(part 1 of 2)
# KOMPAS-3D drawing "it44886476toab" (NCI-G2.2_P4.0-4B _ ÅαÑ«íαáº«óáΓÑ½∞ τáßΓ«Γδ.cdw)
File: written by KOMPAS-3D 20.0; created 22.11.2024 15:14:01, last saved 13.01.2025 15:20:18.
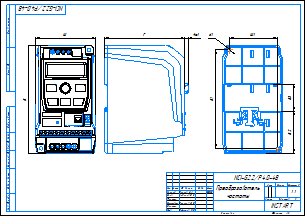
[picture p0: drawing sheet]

Sheet 1: A3, landscape

Document properties: Автор: admin; Полное имя файла: C:\Уралов Работа\Уралов (локальная)\ПЧ\! Китай 3Д-модель NCI\NCI 0.75-2.2 4B\NCI 0.75-2.2 4B.m3d

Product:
- Part/product: it44886476toab
    Масса: 2.32322
  - Body: Тело 17
      Масса: 0.0117014
  - Body: Тело 374
      Масса: 5.48304e-05
  - Body: Тело 265
      Масса: 1.32696e-05
  - Body: Тело 266
      Масса: 1.7366e-05
  - Body: Тело 267
      Масса: 1.7366e-05
  - Body: Тело 103
      Масса: 1.32696e-05
  - Body: Тело 573
      Масса: 4.06595e-05
  - Body: Тело 348
      Масса: 1.32696e-05
  - Body: Тело 270
      Масса: 1.7366e-05
  - Body: Тело 77
      Масса: 1.32696e-05
  - Body: Тело 244
      Масса: 1.65581e-05
  - Body: Тело 536
      Масса: 0.000158536
  - Body: Тело 377
      Масса: 1.65581e-05
  - Body: Тело 272
      Масса: 1.7366e-05
  - Body: Тело 273
      Масса: 5.48304e-05
  - Body: Тело 238
      Масса: 1.7366e-05
  - Body: Тело 274
      Масса: 1.7366e-05
  - Body: Тело 277
      Масса: 1.7366e-05
  - Body: Тело 530
      Масса: 5.61948e-05
  - Body: Тело 278
      Масса: 1.7366e-05
  - Body: Тело 282
      Масса: 1.7366e-05
  - Body: Тело 477
      Масса: 1.51773e-05
  - Body: Тело 526
      Масса: 5.61948e-05
  - Body: Тело 391
      Масса: 1.32696e-05
  - Body: Тело 285
      Масса: 5.48304e-05
  - Body: Тело 287
      Масса: 1.32696e-05
  - Body: Тело 290
      Масса: 0.000413213
  - Body: Тело 269
      Масса: 5.48304e-05
  - Body: Тело 292
      Масса: 1.7366e-05
  - Body: Тело 33
      Масса: 0.00516019
  - Body: Тело 252
      Масса: 5.48304e-05
  - Body: Тело 294
      Масса: 0.000413213
  - Body: Тело 297
      Масса: 3.64631e-05
  - Body: Тело 299
      Масса: 3.64028e-05
  - Body: Тело 283
      Масса: 1.7366e-05
  - Body: Тело 300
      Масса: 1.65581e-05
  - Body: Тело 303
      Масса: 1.65581e-05
  - Body: Тело 516
      Масса: 0.00507377
  - Body: Тело 384
      Масса: 5.48304e-05
  - Body: Тело 360
      Масса: 1.32696e-05
  - Body: Тело 347
      Масса: 1.32696e-05
  - Body: Тело 304
      Масса: 1.65581e-05
  - Body: Тело 307
      Масса: 0.000213463
  - Body: Тело 308
      Масса: 0.000413213
  - Body: Тело 180
      Масса: 1.32696e-05
  - Body: Тело 240
      Масса: 1.7366e-05
  - Body: Тело 309
      Масса: 1.32696e-05
  - Body: Тело 473
      Масса: 0.00425494
  - Body: Тело 311
      Масса: 5.48304e-05
  - Body: Тело 122
      Масса: 1.65581e-05
  - Body: Тело 560
      Масса: 1.65581e-05
  - Body: Тело 312
      Масса: 5.48304e-05
  - Body: Тело 317
      Масса: 1.32696e-05
  - Body: Тело 318
      Масса: 1.32696e-05
  - Body: Тело 321
      Масса: 1.32696e-05
  - Body: Тело 324
      Масса: 1.32696e-05
  - Body: Тело 480
      Масса: 1.51773e-05
  - Body: Тело 288
      Масса: 1.7366e-05
  - Body: Тело 293
      Масса: 5.48304e-05
  - Body: Тело 325
      Масса: 1.32696e-05
  - Body: Тело 99
      Масса: 1.65581e-05
  - Body: Тело 617
      Масса: 1.63919e-05
  - Body: Тело 327
      Масса: 1.32696e-05
  - Body: Тело 31
      Масса: 0.0078835
  - Body: Тело 100
      Масса: 1.65581e-05
  - Body: Тело 105
      Масса: 1.32696e-05
  - Body: Тело 328
      Масса: 1.7366e-05
  - Body: Тело 301
      Масса: 1.65581e-05
  - Body: Тело 331
      Масса: 1.7366e-05
  - Body: Тело 332
      Масса: 1.7366e-05
  - Body: Тело 446
      Масса: 0.000307437
  - Body: Тело 337
      Масса: 1.7366e-05
  - Body: Тело 338
      Масса: 1.7366e-05
  - Body: Тело 570
      Масса: 4.06595e-05
  - Body: Тело 340
      Масса: 1.32696e-05
  - Body: Тело 196
      Масса: 1.32696e-05
  - Body: Тело 357
      Масса: 1.65581e-05
  - Body: Тело 346
      Масса: 1.32696e-05
  - Body: Тело 335
      Масса: 1.32696e-05
  - Body: Тело 281
      Масса: 1.32696e-05
  - Body: Тело 362
      Масса: 1.32696e-05
  - Body: Тело 353
      Масса: 1.7366e-05
  - Body: Тело 355
      Масса: 5.48304e-05
  - Body: Тело 466
      Масса: 0.00829114
  - Body: Тело 358
      Масса: 5.48304e-05
  - Body: Тело 359
      Масса: 1.7366e-05
  - Body: Тело 286
      Масса: 1.7366e-05
  - Body: Тело 86
      Масса: 1.32696e-05
  - Body: Тело 310
      Масса: 1.7366e-05
  - Body: Тело 368
      Масса: 1.32696e-05
  - Body: Тело 370
      Масса: 1.32696e-05
  - Body: Тело 333
      Масса: 1.32696e-05
  - Body: Тело 628
      Масса: 1.51773e-05
  - Body: Тело 371
      Масса: 1.7366e-05
  - Body: Тело 75
      Масса: 1.32696e-05
  - Body: Тело 373
      Масса: 1.32696e-05
  - Body: Тело 375
      Масса: 1.32696e-05
  - Body: Тело 351
      Масса: 2.90876e-05
  - Body: Тело 76
      Масса: 1.65581e-05
  - Body: Тело 259
      Масса: 1.7366e-05
  - Body: Тело 378
      Масса: 0.000413213
  - Body: Тело 95
      Масса: 0.000935996
  - Body: Тело 372
      Масса: 1.7366e-05
  - Body: Тело 322
      Масса: 1.32696e-05
  - Body: Тело 380
      Масса: 1.32696e-05
  - Body: Тело 639
      Масса: 1.63919e-05
  - Body: Тело 385
      Масса: 1.32696e-05
  - Body: Тело 291
      Масса: 0.000213463
  - Body: Тело 386
      Масса: 1.32696e-05
  - Body: Тело 229
      Масса: 1.32696e-05
  - Body: Тело 388
      Масса: 1.32696e-05
  - Body: Тело 389
      Масса: 1.65581e-05
  - Body: Тело 93
      Масса: 3.83377e-05
  - Body: Тело 390
      Масса: 1.65581e-05
  - Body: Тело 143
      Масса: 1.32696e-05
  - Body: Тело 394
      Масса: 1.32696e-05
  - Body: Тело 395
      Масса: 1.32696e-05
  - Body: Тело 354
      Масса: 0.000213463
  - Body: Тело 396
      Масса: 1.7366e-05
  - Body: Тело 397
      Масса: 1.32696e-05
  - Body: Тело 398
      Масса: 1.65581e-05
  - Body: Тело 479
      Масса: 1.51773e-05
  - Body: Тело 402
      Масса: 1.7366e-05
  - Body: Тело 59
      Масса: 1.32696e-05
  - Body: Тело 339
      Масса: 1.32696e-05
  - Body: Тело 404
      Масса: 1.32696e-05
  - Body: Тело 89
      Масса: 0.00142218
  - Body: Тело 406
      Масса: 1.65581e-05
  - Body: Тело 393
      Масса: 1.32696e-05
  - Body: Тело 52
      Масса: 1.32696e-05
  - Body: Тело 407
      Масса: 5.48304e-05
  - Body: Тело 97
      Масса: 0.0015961
  - Body: Тело 410
      Масса: 5.48304e-05
  - Body: Тело 636
      Масса: 1.65581e-05
  - Body: Тело 412
      Масса: 1.7366e-05
  - Body: Тело 413
      Масса: 1.32696e-05
  - Body: Тело 414
      Масса: 1.32696e-05
  - Body: Тело 537
      Масса: 0.000158536
  - Body: Тело 415
      Масса: 1.7366e-05
  - Body: Тело 235
      Масса: 1.7366e-05
  - Body: Тело 419
      Масса: 1.32696e-05
  - Body: Тело 648
      Масса: 0.00426189
  - Body: Тело 420
      Масса: 1.7366e-05
  - Body: Тело 186
      Масса: 1.32696e-05
  - Body: Тело 422
      Масса: 5.48304e-05
  - Body: Тело 381
      Масса: 1.7366e-05
  - Body: Тело 423
      Масса: 1.32696e-05
  - Body: Тело 424
      Масса: 1.7366e-05
  - Body: Тело 98
      Масса: 1.65581e-05
  - Body: Тело 305
      Масса: 1.65581e-05
  - Body: Тело 425
      Масса: 1.32696e-05
  - Body: Тело 365
      Масса: 1.32696e-05
  - Body: Тело 271
      Масса: 1.32696e-05
  - Body: Тело 206
      Масса: 1.32696e-05
  - Body: Тело 429
      Масса: 0.146258
  - Body: Тело 334
      Масса: 1.7366e-05
  - Body: Тело 430
      Масса: 0.146258
  - Body: Тело 350
      Масса: 1.7366e-05
  - Body: Тело 345
      Масса: 1.32696e-05
  - Body: Тело 431
      Масса: 0.146258
  - Body: Тело 364
      Масса: 1.32696e-05
  - Body: Тело 329
      Масса: 1.32696e-05
  - Body: Тело 434
      Масса: 0.000355433
  - Body: Тело 5
      Масса: 0.000355433
  - Body: Тело 124
      Масса: 1.65581e-05
  - Body: Тело 344
      Масса: 1.32696e-05
  - Body: Тело 436
      Масса: 0.000355433
  - Body: Тело 439
      Масса: 0.00113358
  - Body: Тело 606
      Масса: 0.000137594
  - Body: Тело 323
      Масса: 1.32696e-05
  - Body: Тело 441
      Масса: 0.00113358
  - Body: Тело 442
      Масса: 0.000355433
  - Body: Тело 554
      Масса: 4.06595e-05
  - Body: Тело 444
      Масса: 0.000355433
  - Body: Тело 246
      Масса: 1.65581e-05
  - Body: Тело 445
      Масса: 0.00113358
  - Body: Тело 438
      Масса: 0.000355433
  - Body: Тело 106
      Масса: 1.32696e-05
  - Body: Тело 508
      Масса: 1.51773e-05
  - Body: Тело 577
      Масса: 1.7366e-05
  - Body: Тело 392
      Масса: 1.32696e-05
  - Body: Тело 193
      Масса: 1.32696e-05
  - Body: Тело 448
      Масса: 0.000307437
  - Body: Тело 481
      Масса: 1.51773e-05
  - Body: Тело 450
      Масса: 6.34685e-05
  - Body: Тело 222
      Масса: 1.32696e-05
  - Body: Тело 315
      Масса: 1.7366e-05
  - Body: Тело 452
      Масса: 1.63919e-05
  - Body: Тело 53
      Масса: 1.32696e-05
  - Body: Тело 401
      Масса: 1.32696e-05
  - Body: Тело 418
      Масса: 1.7366e-05
  - Body: Тело 517
      Масса: 0.00106884
  - Body: Тело 417
      Масса: 1.32696e-05
  - Body: Тело 453
      Масса: 1.63919e-05
  - Body: Тело 454
      Масса: 0.000382752
  - Body: Тело 428
      Масса: 0.146258
  - Body: Тело 455
      Масса: 1.51773e-05
  - Body: Тело 539
      Масса: 1.51773e-05
  - Body: Тело 457
      Масса: 1.51773e-05
  - Body: Тело 459
      Масса: 3.90329e-05
  - Body: Тело 557
      Масса: 0.00166679
  - Body: Тело 569
      Масса: 1.32696e-05
  - Body: Тело 578
      Масса: 1.32696e-05
  - Body: Тело 626
      Масса: 1.32696e-05
  - Body: Тело 134
      Масса: 1.32696e-05
  - Body: Тело 582
      Масса: 1.65581e-05
  - Body: Тело 203
      Масса: 1.32696e-05
  - Body: Тело 572
      Масса: 1.32696e-05
  - Body: Тело 567
      Масса: 1.32696e-05
  - Body: Тело 207
      Масса: 1.32696e-05
  - Body: Тело 645
      Масса: 1.32696e-05
  - Body: Тело 559
      Масса: 1.65581e-05
  - Body: Тело 152
      Масса: 1.32696e-05
  - Body: Тело 449
      Масса: 0.0658364
  - Body: Тело 316
      Масса: 1.32696e-05
  - Body: Тело 376
      Масса: 1.32696e-05
  - Body: Тело 575
      Масса: 1.32696e-05
  - Body: Тело 576
      Масса: 1.32696e-05
  - Body: Тело 85
      Масса: 1.32696e-05
  - Body: Тело 574
      Масса: 4.06595e-05
  - Body: Тело 399
      Масса: 1.32696e-05
  - Body: Тело 320
      Масса: 1.32696e-05
  - Body: Тело 275
      Масса: 1.7366e-05
  - Body: Тело 213
      Масса: 1.32696e-05
  - Body: Тело 625
      Масса: 1.32696e-05
  - Body: Тело 644
      Масса: 0.000158536
  - Body: Тело 584
      Масса: 4.06595e-05
  - Body: Тело 70
      Масса: 1.65581e-05
  - Body: Тело 588
      Масса: 1.32696e-05
  - Body: Тело 276
      Масса: 1.7366e-05
  - Body: Тело 363
      Масса: 1.32696e-05
  - Body: Тело 474
      Масса: 1.51773e-05
  - Body: Тело 548
      Масса: 2.98222e-05
  - Body: Тело 409
      Масса: 5.48304e-05
  - Body: Тело 472
      Масса: 0.00329327
  - Body: Тело 533
      Масса: 5.61948e-05
  - Body: Тело 647
      Масса: 0.00426189
  - Body: Тело 586
      Масса: 1.32696e-05
  - Body: Тело 262
      Масса: 1.7366e-05
  - Body: Тело 562
      Масса: 0.000382752
  - Body: Тело 379
      Масса: 1.32696e-05
  - Body: Тело 632
      Масса: 1.51773e-05
  - Body: Тело 565
      Масса: 4.06595e-05
  - Body: Тело 118
      Масса: 0.000413213
  - Body: Тело 597
      Масса: 7.12116e-06
  - Body: Тело 613
      Масса: 1.63919e-05
  - Body: Тело 387
      Масса: 1.32696e-05
  - Body: Тело 593
      Масса: 1.32696e-05
  - Body: Тело 408
      Масса: 5.48304e-05
  - Body: Тело 109
      Масса: 1.32696e-05
  - Body: Тело 163
      Масса: 1.32696e-05
  - Body: Тело 488
      Масса: 1.51773e-05
  - Body: Тело 367
      Масса: 1.32696e-05
  - Body: Тело 411
      Масса: 5.48304e-05
  - Body: Тело 583
      Масса: 4.06595e-05
  - Body: Тело 598
      Масса: 7.12116e-06
  - Body: Тело 551
      Масса: 0.000255388
  - Body: Тело 405
      Масса: 1.32696e-05
  - Body: Тело 619
      Масса: 1.32696e-05
  - Body: Тело 361
      Масса: 1.32696e-05
  - Body: Тело 589
      Масса: 1.32696e-05
  - Body: Тело 499
      Масса: 1.51773e-05
  - Body: Тело 440
      Масса: 0.000355433
  - Body: Тело 640
      Масса: 1.63919e-05
  - Body: Тело 150
      Масса: 1.32696e-05
  - Body: Тело 568
      Масса: 1.32696e-05
  - Body: Тело 194
      Масса: 1.32696e-05
  - Body: Тело 251
      Масса: 1.7366e-05
  - Body: Тело 342
      Масса: 0.00166679
  - Body: Тело 604
      Масса: 5.61948e-05
  - Body: Тело 650
      Масса: 0.00426189
  - Body: Тело 161
      Масса: 1.32696e-05
  - Body: Тело 611
      Масса: 0.000158536
  - Body: Тело 210
      Масса: 1.32696e-05
  - Body: Тело 540
      Масса: 1.51773e-05
  - Body: Тело 296
      Масса: 3.6965e-05
  - Body: Тело 601
      Масса: 5.61948e-05
  - Body: Тело 484
      Масса: 0.000158536
  - Body: Тело 622
      Масса: 1.32696e-05
  - Body: Тело 527
      Масса: 0.000141095
  - Body: Тело 624
      Масса: 1.32696e-05
  - Body: Тело 121
      Масса: 0.000413213
  - Body: Тело 600
      Масса: 5.61948e-05
  - Body: Тело 603
      Масса: 5.61948e-05
  - Body: Тело 607
      Масса: 1.32696e-05
  - Body: Тело 289
      Масса: 1.7366e-05
  - Body: Тело 471
      Масса: 0.00329327
  - Body: Тело 313
      Масса: 1.7366e-05
  - Body: Тело 591
      Масса: 7.12116e-06
  - Body: Тело 356
      Масса: 1.65581e-05
  - Body: Тело 306
      Масса: 1.65581e-05
  - Body: Тело 541
      Масса: 0.000158536
  - Body: Тело 511
      Масса: 1.51773e-05
  - Body: Тело 160
      Масса: 1.32696e-05
  - Body: Тело 566
      Масса: 1.32696e-05
  - Body: Тело 563
      Масса: 4.06595e-05
  - Body: Тело 638
      Масса: 1.7366e-05
  - Body: Тело 489
      Масса: 1.51773e-05
  - Body: Тело 456
      Масса: 1.51773e-05
  - Body: Тело 485
      Масса: 0.000158536
  - Body: Тело 284
      Масса: 1.7366e-05
  - Body: Тело 138
      Масса: 2.23009e-05
  - Body: Тело 225
      Масса: 1.32696e-05
  - Body: Тело 546
      Масса: 0.000255388
  - Body: Тело 113
      Масса: 0.000413213
  - Body: Тело 642
      Масса: 3.90329e-05
  - Body: Тело 618
      Масса: 1.63919e-05
  - Body: Тело 525
      Масса: 0.000213463
  - Body: Тело 164
      Масса: 1.32696e-05
  - Body: Тело 253
      Масса: 1.7366e-05
  - Body: Тело 561
      Масса: 1.65581e-05
  - Body: Тело 594
      Масса: 1.32696e-05
  - Body: Тело 482
      Масса: 1.51773e-05
  - Body: Тело 81
      Масса: 1.32696e-05
  - Body: Тело 280
      Масса: 1.32696e-05
  - Body: Тело 494
      Масса: 1.51773e-05
  - Body: Тело 641
      Масса: 3.90329e-05
  - Body: Тело 564
      Масса: 4.06595e-05
  - Body: Тело 633
      Масса: 1.51773e-05
  - Body: Тело 518
      Масса: 0.00166679
  - Body: Тело 620
      Масса: 1.7366e-05
  - Body: Тело 497
      Масса: 1.51773e-05
  - Body: Тело 151
      Масса: 1.65581e-05
  - Body: Тело 302
      Масса: 1.65581e-05
  - Body: Тело 110
      Масса: 1.32696e-05
  - Body: Тело 646
      Масса: 0.000137594
  - Body: Тело 264
      Масса: 1.7366e-05
  - Body: Тело 635
      Масса: 1.65581e-05
  - Body: Тело 608
      Масса: 0.00166679
  - Body: Тело 460
      Масса: 3.90329e-05
  - Body: Тело 403
      Масса: 1.7366e-05
  - Body: Тело 612
      Масса: 0.000158536
  - Body: Тело 492
      Масса: 1.51773e-05
  - Body: Тело 139
      Масса: 0.000194606
  - Body: Тело 400
      Масса: 1.7366e-05
  - Body: Тело 605
      Масса: 5.61948e-05
  - Body: Тело 623
      Масса: 1.32696e-05
  - Body: Тело 117
      Масса: 0.000413213
  - Body: Тело 185
      Масса: 1.32696e-05
  - Body: Тело 631
      Масса: 1.51773e-05
  - Body: Тело 580
      Масса: 1.32696e-05
  - Body: Тело 349
      Масса: 1.7366e-05
  - Body: Тело 621
      Масса: 1.32696e-05
  - Body: Тело 627
      Масса: 0.000255388
  - Body: Тело 531
      Масса: 5.61948e-05
  - Body: Тело 649
      Масса: 0.00426189
  - Body: Тело 585
      Масса: 4.06595e-05
  - Body: Тело 236
      Масса: 1.7366e-05
  - Body: Тело 513
      Масса: 1.51773e-05
  - Body: Тело 426
      Масса: 1.32696e-05
  - Body: Тело 341
      Масса: 0.00166679
  - Body: Тело 470
      Масса: 0.00329329
  - Body: Тело 382
      Масса: 5.48304e-05
  - Body: Тело 227
      Масса: 1.32696e-05
  - Body: Тело 476
      Масса: 1.51773e-05
  - Body: Тело 538
      Масса: 1.51773e-05
  - Body: Тело 596
      Масса: 1.32696e-05
  - Body: Тело 609
      Масса: 1.7366e-05
  - Body: Тело 610
      Масса: 0.00166679
  - Body: Тело 263
      Масса: 1.7366e-05
  - Body: Тело 629
      Масса: 1.51773e-05
  - Body: Тело 336
      Масса: 3.64028e-05
  - Body: Тело 495
      Масса: 1.51773e-05
  - Body: Тело 168
      Масса: 1.32696e-05
  - Body: Тело 298
      Масса: 3.64495e-05
  - Body: Тело 279
      Масса: 1.32696e-05
  - Body: Тело 72
      Масса: 1.65581e-05
  - Body: Тело 500
      Масса: 1.51773e-05
  - Body: Тело 505
      Масса: 1.51773e-05
  - Body: Тело 558
      Масса: 0.00726683
  - Body: Тело 630
      Масса: 1.51773e-05
  - Body: Тело 602
      Масса: 5.61948e-05
  - Body: Тело 556
      Масса: 0.00166679
  - Body: Тело 555
      Масса: 0.00166679
  - Body: Тело 634
      Масса: 1.51773e-05
  - Body: Тело 435
      Масса: 0.00113358
  - Body: Тело 416
      Масса: 1.7366e-05
  - Body: Тело 190
      Масса: 1.32696e-05
  - Body: Тело 330
      Масса: 1.7366e-05
  - Body: Тело 28
      Масса: 0.00135688
  - Body: Тело 553
      Масса: 4.06595e-05
  - Body: Тело 176
      Масса: 1.32696e-05
  - Body: Тело 552
      Масса: 4.06595e-05
  - Body: Тело 534
      Масса: 1.32696e-05
  - Body: Тело 595
      Масса: 1.32696e-05
  - Body: Тело 23
      Масса: 0.0243258
  - Body: Тело 247
      Масса: 1.7366e-05
  - Body: Тело 314
      Масса: 1.7366e-05
  - Body: Тело 126
      Масса: 0.000512664
  - Body: Тело 157
      Масса: 1.32696e-05
  - Body: Тело 550
      Масса: 0.000255388
  - Body: Тело 32
      Масса: 0.0135217
  - Body: Тело 592
      Масса: 7.12116e-06
  - Body: Тело 366
      Масса: 1.7366e-05
  - Body: Тело 504
      Масса: 1.51773e-05
  - Body: Тело 258
      Масса: 1.7366e-05
  - Body: Тело 421
      Масса: 1.7366e-05
  - Body: Тело 35
      Масса: 0.262997
  - Body: Тело 204
      Масса: 1.32696e-05
  - Body: Тело 549
      Масса: 0.000255388
  - Body: Тело 257
      Масса: 1.7366e-05
  - Body: Тело 614
      Масса: 1.63919e-05
  - Body: Тело 547
      Масса: 0.000255388
  - Body: Тело 41
      Масса: 0.0119524
  - Body: Тело 71
      Масса: 1.65581e-05
  - Body: Тело 506
      Масса: 1.51773e-05
  - Body: Тело 545
      Масса: 1.51773e-05
  - Body: Тело 145
      Масса: 1.32696e-05
  - Body: Тело 461
      Масса: 0.000404362
  - Body: Тело 502
      Масса: 1.51773e-05
  - Body: Тело 352
      Масса: 2.90876e-05
  - Body: Тело 120
      Масса: 0.000413213
  - Body: Тело 295
      Масса: 1.65581e-05
  - Body: Тело 544
      Масса: 0.000158536
  - Body: Тело 469
      Масса: 0.0113891
  - Body: Тело 146
      Масса: 1.32696e-05
  - Body: Тело 149
      Масса: 1.32696e-05
  - Body: Тело 615
      Масса: 1.63919e-05
  - Body: Тело 543
      Масса: 0.000158536
  - Body: Тело 542
      Масса: 0.000158536
  - Body: Тело 462
      Масса: 0.000404362
  - Body: Тело 616
      Масса: 1.63919e-05
  - Body: Тело 343
      Масса: 0.00166679
  - Body: Тело 532
      Масса: 5.61948e-05
  - Body: Тело 493
      Масса: 1.51773e-05
  - Body: Тело 529
      Масса: 5.61948e-05
  - Body: Тело 579
      Масса: 0.00017125
  - Body: Тело 200
      Масса: 1.32696e-05
  - Body: Тело 239
      Масса: 5.48304e-05
  - Body: Тело 443
      Масса: 0.00113358
  - Body: Тело 216
      Масса: 0.000280294
  - Body: Тело 468
      Масса: 0.0253857
  - Body: Тело 64
      Масса: 1.65581e-05
  - Body: Тело 528
      Масса: 0.000141095
  - Body: Тело 599
      Масса: 7.12116e-06
  - Body: Тело 590
      Масса: 1.32696e-05
  - Body: Тело 191
      Масса: 1.32696e-05
  - Body: Тело 523
      Масса: 0.000255388
  - Body: Тело 458
      Масса: 1.51773e-05
  - Body: Тело 319
      Масса: 1.32696e-05
  - Body: Тело 49
      Масса: 0.00944
  - Body: Тело 522
      Масса: 1.65581e-05
  - Body: Тело 521
      Масса: 1.32696e-05
  - Body: Тело 571
      Масса: 0.00166679
  - Body: Тело 509
      Масса: 1.51773e-05
  - Body: Тело 326
      Масса: 1.32696e-05
  - Body: Тело 520
      Масса: 5.48304e-05
  - Body: Тело 427
      Масса: 1.32696e-05
  - Body: Тело 519
      Масса: 1.7366e-05
  - Body: Тело 637
      Масса: 1.51773e-05
  - Body: Тело 524
      Масса: 1.65581e-05
  - Body: Тело 432
      Масса: 0.000118347
  - Body: Тело 487
      Масса: 1.65581e-05
  - Body: Тело 510
      Масса: 1.51773e-05
  - Body: Тело 515
      Масса: 0.00507372
  - Body: Тело 512
      Масса: 1.51773e-05
  - Body: Тело 155
      Масса: 1.32696e-05
  - Body: Тело 587
      Масса: 1.32696e-05
  - Body: Тело 174
      Масса: 1.65581e-05
  - Body: Тело 507
      Масса: 1.51773e-05
  - Body: Тело 12
      Масса: 0.000703761
  - Body: Тело 187
      Масса: 1.32696e-05
  - Body: Тело 447
      Масса: 0.000307437
  - Body: Тело 503
      Масса: 1.51773e-05
  - Body: Тело 501
      Масса: 1.51773e-05
  - Body: Тело 369
      Масса: 1.32696e-05
  - Body: Тело 60
      Масса: 1.32696e-05
  - Body: Тело 498
      Масса: 1.51773e-05
  - Body: Тело 535
      Масса: 1.52051e-05
  - Body: Тело 437
      Масса: 0.00113358
  - Body: Тело 496
      Масса: 1.51773e-05
  - Body: Тело 433
      Масса: 0.000118347
  - Body: Тело 491
      Масса: 1.65581e-05
  - Body: Тело 490
      Масса: 1.51773e-05
  - Body: Тело 581
      Масса: 1.65581e-05
  - Body: Тело 486
      Масса: 0.000158536
  - Body: Тело 483
      Масса: 1.51773e-05
  - Body: Тело 514
      Масса: 1.51773e-05
  - Body: Тело 643
      Масса: 0.000158536
  - Body: Тело 125
      Масса: 1.65581e-05
  - Body: Тело 383
      Масса: 0.000340816
  - Body: Тело 465
      Масса: 0.00829114
  - Body: Тело 478
      Масса: 1.51773e-05
  - Body: Тело 451
      Масса: 6.34685e-05
  - Body: Тело 475
      Масса: 1.51773e-05
  - Body: Тело 467
      Масса: 0.00436982
  - Body: Тело 268
      Масса: 5.48304e-05
  - Body: Тело 464
      Масса: 0.00829425
  - Body: Тело 226
      Масса: 0.000413213
  - Body: Тело 463
      Масса: 0.000404362
  - Body: Тело 170
      Масса: 1.32696e-05
  - Body: Тело 261
      Масса: 3.83377e-05
  - Body: Тело 260
      Масса: 1.7366e-05
  - Body: Тело 167
      Масса: 1.32696e-05
  - Body: Тело 256
      Масса: 1.7366e-05
  - Body: Тело 119
      Масса: 0.000413213
  - Body: Тело 255
      Масса: 1.7366e-05
  - Body: Тело 254
      Масса: 1.32696e-05
  - Body: Тело 250
      Масса: 1.7366e-05
  - Body: Тело 249
      Масса: 1.7366e-05
  - Body: Тело 248
      Масса: 1.7366e-05
  - Body: Тело 19
      Масса: 0.0117014
  - Body: Тело 114
      Масса: 0.000413213
  - Body: Тело 234
      Масса: 1.7366e-05
  - Body: Тело 245
      Масса: 1.65581e-05
  - Body: Тело 243
      Масса: 1.65581e-05
  - Body: Тело 242
      Масса: 1.65581e-05
  - Body: Тело 65
      Масса: 1.65581e-05
  - Body: Тело 241
      Масса: 0.000424983
  - Body: Тело 141
      Масса: 0.000213463
  - Body: Тело 237
      Масса: 1.7366e-05
  - Body: Тело 1
      Масса: 0.00113358
  - Body: Тело 233
      Масса: 1.7366e-05
  - Body: Тело 232
      Масса: 5.48304e-05
  - Body: Тело 231
      Масса: 0.00398049
  - Body: Тело 230
      Масса: 1.32696e-05
  - Body: Тело 184
      Масса: 1.32696e-05
  - Body: Тело 228
      Масса: 1.32696e-05
  - Body: Тело 224
      Масса: 1.32696e-05
  - Body: Тело 162
      Масса: 1.65581e-05
  - Body: Тело 223
      Масса: 1.32696e-05
  - Body: Тело 221
      Масса: 1.65581e-05
  - Body: Тело 220
      Масса: 1.32696e-05
  - Body: Тело 219
      Масса: 1.32696e-05
  - Body: Тело 218
      Масса: 1.32696e-05
  - Body: Тело 217
      Масса: 1.32696e-05
  - Body: Тело 215
      Масса: 1.65581e-05
  - Body: Тело 9
      Масса: 0.000703761
  - Body: Тело 214
      Масса: 1.32696e-05
  - Body: Тело 212
      Масса: 1.32696e-05
  - Body: Тело 211
      Масса: 1.32696e-05
  - Body: Тело 209
      Масса: 1.32696e-05
  - Body: Тело 208
      Масса: 1.7366e-05
  - Body: Тело 205
      Масса: 1.32696e-05
  - Body: Тело 202
      Масса: 1.32696e-05
  - Body: Тело 201
      Масса: 1.32696e-05
  - Body: Тело 29
      Масса: 0.00135688
  - Body: Тело 199
      Масса: 1.32696e-05
  - Body: Тело 198
      Масса: 1.32696e-05
  - Body: Тело 197
      Масса: 1.32696e-05
  - Body: Тело 195
      Масса: 1.32696e-05
  - Body: Тело 192
      Масса: 1.32696e-05
  - Body: Тело 189
      Масса: 1.32696e-05
  - Body: Тело 188
      Масса: 1.32696e-05
  - Body: Тело 183
      Масса: 1.32696e-05
  - Body: Тело 182
      Масса: 1.32696e-05
  - Body: Тело 181
      Масса: 1.32696e-05
  - Body: Тело 179
      Масса: 1.32696e-05
  - Body: Тело 178
      Масса: 1.32696e-05
  - Body: Тело 44
      Масса: 0.0119524
  - Body: Тело 50
      Масса: 0.00101975
  - Body: Тело 177
      Масса: 1.32696e-05
  - Body: Тело 175
      Масса: 1.32696e-05
  - Body: Тело 45
      Масса: 0.0267013
  - Body: Тело 137
      Масса: 1.32696e-05
  - Body: Тело 173
      Масса: 1.32696e-05
  - Body: Тело 172
      Масса: 1.65581e-05
  - Body: Тело 153
      Масса: 1.32696e-05
  - Body: Тело 171
      Масса: 1.32696e-05
  - Body: Тело 169
      Масса: 1.32696e-05
  - Body: Тело 140
      Масса: 0.000213463
  - Body: Тело 166
      Масса: 1.32696e-05
  - Body: Тело 165
      Масса: 1.65581e-05
  - Body: Тело 159
      Масса: 1.32696e-05
  - Body: Тело 116
      Масса: 0.000413213
  - Body: Тело 158
      Масса: 1.32696e-05
  - Body: Тело 156
      Масса: 1.32696e-05
  - Body: Тело 154
      Масса: 1.32696e-05
  - Body: Тело 148
      Масса: 1.32696e-05
  - Body: Тело 147
      Масса: 1.32696e-05
  - Body: Тело 24
      Масса: 0.0110484
  - Body: Тело 62
      Масса: 1.32696e-05
  - Body: Тело 144
      Масса: 1.32696e-05
  - Body: Тело 142
      Масса: 0.000213463
  - Body: Тело 136
      Масса: 1.32696e-05
  - Body: Тело 135
      Масса: 1.32696e-05
  - Body: Тело 38
      Масса: 0.00631989
  - Body: Тело 133
      Масса: 1.32696e-05
  - Body: Тело 132
      Масса: 1.32696e-05
  - Body: Тело 131
      Масса: 1.32696e-05
  - Body: Тело 16
      Масса: 0.000703761
  - Body: Тело 130
      Масса: 1.32696e-05
  - Body: Тело 112
      Масса: 0.000413213
  - Body: Тело 129
      Масса: 1.32696e-05
  - Body: Тело 128
      Масса: 1.32696e-05
  - Body: Тело 127
      Масса: 1.32696e-05
  - Body: Тело 123
      Масса: 1.65581e-05
  - Body: Тело 115
      Масса: 0.000413213
  - Body: Тело 111
      Масса: 0.000194606
  - Body: Тело 108
      Масса: 1.32696e-05
  - Body: Тело 107
      Масса: 1.32696e-05
  - Body: Тело 104
      Масса: 1.32696e-05
  - Body: Тело 102
      Масса: 1.32696e-05
  - Body: Тело 90
      Масса: 0.000966482
  - Body: Тело 101
      Масса: 1.32696e-05
  - Body: Тело 96
      Масса: 0.00181049
  - Body: Тело 94
      Масса: 0.00554276
  - Body: Тело 92
      Масса: 3.83377e-05
  - Body: Тело 91
      Масса: 0.0246688
  - Body: Тело 15
      Масса: 0.000703761
  - Body: Тело 88
      Масса: 0.000873873
  - Body: Тело 87
      Масса: 0.000966482
  - Body: Тело 84
      Масса: 1.32696e-05
  - Body: Тело 83
      Масса: 1.32696e-05
  - Body: Тело 82
      Масса: 1.32696e-05
  - Body: Тело 80
      Масса: 1.32696e-05
  - Body: Тело 79
      Масса: 1.32696e-05
  - Body: Тело 78
      Масса: 1.65581e-05
  - Body: Тело 74
      Масса: 1.65581e-05
  - Body: Тело 48
      Масса: 0.00853877
  - Body: Тело 73
      Масса: 1.65581e-05
  - Body: Тело 69
      Масса: 1.65581e-05
  - Body: Тело 68
      Масса: 1.65581e-05
  - Body: Тело 67
      Масса: 1.65581e-05
  - Body: Тело 66
      Масса: 1.65581e-05
  - Body: Тело 63
      Масса: 1.65581e-05
  - Body: Тело 57
      Масса: 1.32696e-05
  - Body: Тело 61
      Масса: 1.32696e-05
  - Body: Тело 58
      Масса: 1.32696e-05
  - Body: Тело 56
      Масса: 1.32696e-05
  - Body: Тело 55
      Масса: 1.32696e-05
  - Body: Тело 54
      Масса: 1.32696e-05
  - Body: Тело 51
      Масса: 1.32696e-05
  - Body: Тело 47
      Масса: 0.551587
  - Body: Тело 46
      Масса: 0.0119034
  - Body: Тело 43
      Масса: 0.0119524
  - Body: Тело 42
      Масса: 0.0119524
  - Body: Тело 40
      Масса: 0.0119524
  - Body: Тело 39
      Масса: 0.0119524
  - Body: Тело 37
      Масса: 0.0343584
  - Body: Тело 36
      Масса: 0.0668131
  - Body: Тело 34
      Масса: 0.00831628
  - Body: Тело 30
      Масса: 0.000935996
  - Body: Тело 27
      Масса: 0.00135688
  - Body: Тело 26
      Масса: 0.00135688
  - Body: Тело 25
      Масса: 0.00135688
  - Body: Тело 22
      Масса: 0.0636504
  - Body: Тело 21
      Масса: 0.0864411
  - Body: Тело 20
      Масса: 0.120334
  - Body: Тело 18
      Масса: 0.0117014
  - Body: Тело 14
      Масса: 0.000703761
  - Body: Тело 13
      Масса: 0.000703761
  - Body: Тело 11
      Масса: 0.000703761
  - Body: Тело 10
      Масса: 0.0160396
  - Body: Тело 8
      Масса: 0.000703761
  - Body: Тело 7
      Масса: 0.000703761
  - Body: Тело 6
      Масса: 0.000355433
  - Body: Тело 4
      Масса: 0.000355433
  - Body: Тело 3
      Масса: 0.00113358
  - Body: Тело 2
      Масса: 0.00113358

Title block, sheet 1: Наименование: Преобразователь / частоты; designation: NCI-G2.2/P4.0-4B; Количество листов документа: 1; organisation: INSTART; cell 10: Согласовано; Форматы листов документа: A3; stored path: P:\INSTART\Технический отдел\ОР\Прочие задачи\КД на номенклатурный ряд\КД на типоразмеры ПЧ\NCI\NCI-G0.75_P1.5-4B\NCI-G0.75_P1.5-4B _ Преобразователь частоты.cdw; Разработал: Уралов Д.А.; Проверил: Андреев Н.В.; Подписал: Смелков Ж.Е.; Утвердил: Ефремов И.Н.; Разработал, date: 13.01.25

Views: Вид 1
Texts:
  Кривая без истории:10000
  Кривая без истории:10001
  Кривая без истории:10002
  Кривая без истории:10003
  Кривая без истории:10004
  Кривая без истории:10005
  Кривая без истории:10006
  Кривая без истории:10007
  Кривая без истории:10008
  Кривая без истории:10009
  Кривая без истории:10010
  Кривая без истории:10011
  Кривая без истории:10012
  Кривая без истории:10013
  Кривая без истории:10014
  Кривая без истории:10015
  Кривая без истории:10016
  Кривая без истории:10017
  Кривая без истории:10018
  Кривая без истории:10019
  Кривая без истории:10020
  Кривая без истории:10021
  Кривая без истории:10022
  Кривая без истории:10023
  Кривая без истории:10024
  Кривая без истории:10025
  Кривая без истории:10026
  Кривая без истории:10027
  Кривая без истории:10028
  Кривая без истории:10029
  Кривая без истории:10030
  Кривая без истории:10031
  Кривая без истории:10032
  Кривая без истории:10033
  Кривая без истории:10034
  Кривая без истории:10035
  Кривая без истории:10036
  Кривая без истории:10037
  Кривая без истории:10038
  Кривая без истории:10039
  Кривая без истории:10040
  Кривая без истории:10041
  Кривая без истории:10042
  Кривая без истории:10043
  Кривая без истории:10044
  Кривая без истории:10045
  Кривая без истории:10046
  Кривая без истории:10047
  Кривая без истории:10048
  Кривая без истории:10049
  Кривая без истории:10050
  Кривая без истории:10051
  Кривая без истории:10052
  Кривая без истории:10053
  Кривая без истории:10054
  Кривая без истории:10055
  Кривая без истории:10056
  Кривая без истории:10057
  Кривая без истории:10058
  Кривая без истории:10059
  Кривая без истории:10060
  Кривая без истории:10061
  Кривая без истории:10062
  Кривая без истории:10063
  Кривая без истории:10064
  Кривая без истории:10065
  Кривая без истории:10066
  Кривая без истории:10067
  Кривая без истории:10068
  Кривая без истории:10069
  Кривая без истории:10070
  Кривая без истории:10071
  Кривая без истории:10072
  Кривая без истории:10073
  Кривая без истории:10074
  Кривая без истории:10075
  Кривая без истории:10076
  Кривая без истории:10077
  Кривая без истории:10078
  Кривая без истории:10079
  Кривая без истории:10080
  Кривая без истории:10081
  Кривая без истории:10082
  Кривая без истории:10083
  Кривая без истории:10084
  Кривая без истории:10085
  Кривая без истории:10086
  Кривая без истории:10087
  Кривая без истории:10088
  Кривая без истории:10089
  Кривая без истории:10090
  Кривая без истории:10091
  Кривая без истории:10092
  Кривая без истории:10093
  Кривая без истории:10094
  Кривая без истории:10095
  Кривая без истории:10096
  Кривая без истории:10097
  Кривая без истории:10098
  Кривая без истории:10099
  Кривая без истории:10100
  Кривая без истории:10101
  Кривая без истории:10102
  Кривая без истории:10103
  Кривая без истории:10104
  Кривая без истории:10105
  Кривая без истории:10106
  Кривая без истории:10107
  Кривая без истории:10108
  Кривая без истории:10109
  Кривая без истории:10110
  Кривая без истории:10111
  Кривая без истории:10112
  Кривая без истории:10113
  Кривая без истории:10114
  Кривая без истории:10115
  Кривая без истории:10116
  Кривая без истории:10117
  Кривая без истории:10118
  Кривая без истории:10119
  Кривая без истории:10120
  Кривая без истории:10121
  Кривая без истории:10122
  Кривая без истории:10123
  Кривая без истории:10124
  Кривая без истории:10125
  Кривая без истории:10126
  Кривая без истории:10127
  Кривая без истории:10128
  Кривая без истории:10129
  Кривая без истории:10130
  Кривая без истории:10131
  Кривая без истории:10132
  Кривая без истории:10133
  Кривая без истории:10134
  Кривая без истории:10135
  Кривая без истории:10136
  Кривая без истории:10137
  Кривая без истории:10138
  Кривая без истории:10139
  Кривая без истории:10140
  Кривая без истории:10141
  Кривая без истории:10142
  Кривая без истории:10143
  Кривая без истории:10144
  Кривая без истории:10145
  Кривая без истории:10146
  Кривая без истории:10147
  Кривая без истории:10148
  Кривая без истории:10149
  Кривая без истории:10150
  Кривая без истории:10151
  Кривая без истории:10152
  Кривая без истории:10153
  Кривая без истории:10154
  Кривая без истории:10155
  Кривая без истории:10156
  Кривая без истории:10157
  Кривая без истории:10158
  Кривая без истории:10159
  Кривая без истории:10160
  Кривая без истории:10161
  Кривая без истории:10162
  Кривая без истории:10163
  Кривая без истории:10164
  Кривая без истории:10165
  Кривая без истории:10166
  Кривая без истории:10167
  Кривая без истории:10168
  Кривая без истории:10169
  Кривая без истории:10170
  Кривая без истории:10171
  Кривая без истории:10172
  Кривая без истории:10173
  Кривая без истории:10174
  Кривая без истории:10175
  Кривая без истории:10176
  Кривая без истории:10177
  Кривая без истории:10178
  Кривая без истории:10179
  Кривая без истории:10180
  Кривая без истории:10181
  Кривая без истории:10182
  Кривая без истории:10183
  Кривая без истории:10184
  Кривая без истории:10185
  Кривая без истории:10186
  Кривая без истории:10187
  Кривая без истории:10188
  Кривая без истории:10189
  Кривая без истории:10190
  Кривая без истории:10191
  Кривая без истории:10192
  Кривая без истории:10193
  Кривая без истории:10194
  Кривая без истории:10195
  Кривая без истории:10196
  Кривая без истории:10197
  Кривая без истории:10198
  Кривая без истории:10199
  Кривая без истории:10200
  Кривая без истории:10201
  Кривая без истории:10202
  Кривая без истории:10203
  Кривая без истории:10204
  Кривая без истории:10205
  Кривая без истории:10206
  Кривая без истории:10207
  Кривая без истории:10208
  Кривая без истории:10209
  Кривая без истории:10210
  Кривая без истории:10211
  Кривая без истории:10212
  Кривая без истории:10213
  Кривая без истории:10214
  Кривая без истории:10215
  Кривая без истории:10216
  Кривая без истории:10217
  Кривая без истории:10218
  Кривая без истории:10219
  Кривая без истории:10220
  Кривая без истории:10221
  Кривая без истории:10222
  Кривая без истории:10223
  Кривая без истории:10224
  Кривая без истории:10225
  Кривая без истории:10226
  Кривая без истории:10227
  Кривая без истории:10228
  Кривая без истории:10229
  Кривая без истории:10230
  Кривая без истории:10231
  Кривая без истории:10232
  Кривая без истории:10233
  Кривая без истории:10234
  Кривая без истории:10235
  Кривая без истории:10236
  Кривая без истории:10237
  Кривая без истории:10238
  Кривая без истории:10239
  Кривая без истории:10240
  Кривая без истории:10241
  Кривая без истории:10242
  Кривая без истории:10243
  Кривая без истории:10244
  Кривая без истории:10245
  Кривая без истории:10246
  Кривая без истории:10247
  Кривая без истории:10248
  Кривая без истории:10249
  Кривая без истории:10250
  Кривая без истории:10251
  Кривая без истории:10252
  Кривая без истории:10253
  Кривая без истории:10254
  Кривая без истории:10255
  Кривая без истории:10256
  Кривая без истории:10257
  Кривая без истории:10258
  Кривая без истории:10259
  Кривая без истории:10260
  Кривая без истории:10261
  Кривая без истории:10262
  Кривая без истории:10263
  Кривая без истории:10264
  Кривая без истории:10265
  Кривая без истории:10266
  Кривая без истории:10267
  Кривая без истории:10268
  Кривая без истории:10269
  Кривая без истории:10270
  Кривая без истории:10271
  Кривая без истории:10272
  Кривая без истории:10273
  Кривая без истории:10274
  Кривая без истории:10275
  Кривая без истории:10276
  Кривая без истории:10277
  Кривая без истории:10278
  Кривая без истории:10279
  Кривая без истории:10280
  Кривая без истории:10281
  Кривая без истории:10282
  Кривая без истории:10283
  Кривая без истории:10284
  Кривая без истории:10285
  Кривая без истории:10286
  Кривая без истории:10287
  Кривая без истории:10288
  Кривая без истории:10289
  Кривая без истории:10290
  Кривая без истории:10291
  Кривая без истории:10292
  Кривая без истории:10293
  Кривая без истории:10294
  Кривая без истории:10295
  Кривая без истории:10296
  Кривая без истории:10297
  Кривая без истории:10298
  Кривая без истории:10299
  Кривая без истории:10300
  Кривая без истории:10301
  Кривая без истории:10302
  Кривая без истории:10303
  Кривая без истории:10304
  Кривая без истории:10305
  Кривая без истории:10306
  Кривая без истории:10307
  Кривая без истории:10308
  Кривая без истории:10309
  Кривая без истории:10310
  Кривая без истории:10311
  Кривая без истории:10312
  Кривая без истории:10313
  Кривая без истории:10314
  Кривая без истории:10315
  Кривая без истории:10316
  Кривая без истории:10317
  Кривая без истории:10318
  Кривая без истории:10319
  Кривая без истории:10320
  Кривая без истории:10321
  Кривая без истории:10322
  Кривая без истории:10323
  Кривая без истории:10324
  Кривая без истории:10325
  Кривая без истории:10326
  Кривая без истории:10327
  Кривая без истории:10328
  Кривая без истории:10329
  Кривая без истории:10330
  Кривая без истории:10331
  Кривая без истории:10332
  Кривая без истории:10333
  Кривая без истории:10334
  Кривая без истории:10335
  Кривая без истории:10336
  Кривая без истории:10337
  Кривая без истории:10338
  Кривая без истории:10339
  Кривая без истории:10340
  Кривая без истории:10341
  Кривая без истории:10342
  Кривая без истории:10343
  Кривая без истории:10344
  Кривая без истории:10345
  Кривая без истории:10346
  Кривая без истории:10347
  Кривая без истории:10348
  Кривая без истории:10349
  Кривая без истории:10350
  Кривая без истории:10351
  Кривая без истории:10352
  Кривая без истории:10353
  Кривая без истории:10354
  Кривая без истории:10355
  Кривая без истории:10356
  Кривая без истории:10357
  Кривая без истории:10358
  Кривая без истории:10359
  Кривая без истории:10360
  Кривая без истории:10361
  Кривая без истории:10362
  Кривая без истории:10363
  Кривая без истории:10364
  Кривая без истории:10365
  Кривая без истории:10366
  Кривая без истории:10367
  Кривая без истории:10368
  Кривая без истории:10369
  Кривая без истории:10370
  Кривая без истории:10371
  Кривая без истории:10372
  Кривая без истории:10373
  Кривая без истории:10374
  Кривая без истории:10375
  Кривая без истории:10376
  Кривая без истории:10377
  Кривая без истории:10378
  Кривая без истории:10379
  Кривая без истории:10380
  Кривая без истории:10381
  Кривая без истории:10382
  Кривая без истории:10383
  Кривая без истории:10384
  Кривая без истории:10385
  Кривая без истории:10386
  Кривая без истории:10387
  Кривая без истории:10388
  Кривая без истории:10389
  Кривая без истории:10390
  Кривая без истории:10391
  Кривая без истории:10392
  Кривая без истории:10393
  Кривая без истории:10394
  Кривая без истории:10395
  Кривая без истории:10396
  Кривая без истории:10397
  Кривая без истории:10398
  Кривая без истории:10399
  Кривая без истории:10400
  Кривая без истории:10401
  Кривая без истории:10402
  Кривая без истории:10403
  Кривая без истории:10404
  Кривая без истории:10405
  Кривая без истории:10406
  Кривая без истории:10407
  Кривая без истории:10408
  Кривая без истории:10409
  Кривая без истории:10410
  Кривая без истории:10411
  Кривая без истории:10412
  Кривая без истории:10413
  Кривая без истории:10414
  Кривая без истории:10415
  Кривая без истории:10416
  Кривая без истории:10417
  Кривая без истории:10418
  Кривая без истории:10419
  Кривая без истории:10420
  Кривая без истории:10421
  Кривая без истории:10422
  Кривая без истории:10423
  Кривая без истории:10424
  Кривая без истории:10425
  Кривая без истории:10426
  Кривая без истории:10427
  Кривая без истории:10428
  Кривая без истории:10429
  Кривая без истории:10430
  Кривая без истории:10431
  Кривая без истории:10432
  Кривая без истории:10433
  Кривая без истории:10434
  Кривая без истории:10435
  Кривая без истории:10436
  Кривая без истории:10437
  Кривая без истории:10438
  Кривая без истории:10439
  Кривая без истории:10440
  Кривая без истории:10441
  Кривая без истории:10442
  Кривая без истории:10443
  Кривая без истории:10444
  Кривая без истории:10445
  Кривая без истории:10446
  Кривая без истории:10447
  Кривая без истории:10448
  Кривая без истории:10449
  Кривая без истории:10450
  Кривая без истории:10451
  Кривая без истории:10452
  Кривая без истории:10453
  Кривая без истории:10454
  Кривая без истории:10455
  Кривая без истории:10456
  Кривая без истории:10457
  Кривая без истории:10458
  Кривая без истории:10459
  Кривая без истории:10460
  Кривая без истории:10461
  Кривая без истории:10462
  Кривая без истории:10463
  Кривая без истории:10464
  Кривая без истории:10465
  Кривая без истории:10466
  Кривая без истории:10467
  Кривая без истории:10468
  Кривая без истории:10469
  Кривая без истории:10470
  Кривая без истории:10471
  Кривая без истории:10472
  Кривая без истории:10473
  Кривая без истории:10474
  Кривая без истории:10475
  Кривая без истории:10476
  Кривая без истории:10477
  Кривая без истории:10478
  Кривая без истории:10479
  Кривая без истории:10480
  Кривая без истории:10481
  Кривая без истории:10482
  Кривая без истории:10483
  Кривая без истории:10484
  Кривая без истории:10485
  Кривая без истории:10486
  Кривая без истории:10487
  Кривая без истории:10488
  Кривая без истории:10489
  Кривая без истории:10490
  Кривая без истории:10491
  Кривая без истории:10492
  Кривая без истории:10493
  Кривая без истории:10494
  Кривая без истории:10495
  Кривая без истории:10496
  Кривая без истории:10497
  Кривая без истории:10498
  Кривая без истории:10499
  Кривая без истории:10500
  Кривая без истории:10501
  Кривая без истории:10502
  Кривая без истории:10503
  Кривая без истории:10504
  Кривая без истории:10505
  Кривая без истории:10506
  Кривая без истории:10507
  Кривая без истории:10508
  Кривая без истории:10509
  Кривая без истории:10510
  Кривая без истории:10511
  Кривая без истории:10512
  Кривая без истории:10513
  Кривая без истории:10514
  Кривая без истории:10515
  Кривая без истории:10516
  Кривая без истории:10517
  Кривая без истории:10518
  Кривая без истории:10519
  Кривая без истории:10520
  Кривая без истории:10521
  Кривая без истории:10522
  Кривая без истории:10523
  Кривая без истории:10524
  Кривая без истории:10525
  Кривая без истории:10526
  Кривая без истории:10527
  Кривая без истории:10528
  Кривая без истории:10529
  Кривая без истории:10530
  Кривая без истории:10531
  Кривая без истории:10532
  Кривая без истории:10533
  Кривая без истории:10534
  Кривая без истории:10535
  Кривая без истории:10536
  Кривая без истории:10537
  Кривая без истории:10538
  Кривая без истории:10539
  Кривая без истории:10540
  Кривая без истории:10541
  Кривая без истории:10542
  Кривая без истории:10543
  Кривая без истории:10544
  Кривая без истории:10545
  Кривая без истории:10546
  Кривая без истории:10547
  Кривая без истории:10548
  Кривая без истории:10549
  Кривая без истории:10550
  Кривая без истории:10551
  Кривая без истории:10552
  Кривая без истории:10553
  Кривая без истории:10554
  Кривая без истории:10555
  Кривая без истории:10556
  Кривая без истории:10557
  Кривая без истории:10558
  Кривая без истории:10559
  Кривая без истории:10560
  Кривая без истории:10561
  Кривая без истории:10562
  Кривая без истории:10563
  Кривая без истории:10564
  Кривая без истории:10565
  Кривая без истории:10566
  Кривая без истории:10567
  Кривая без истории:10568
  Кривая без истории:10569
  Кривая без истории:10570
  Кривая без истории:10571
  Кривая без истории:10572
  Кривая без истории:10573
  Кривая без истории:10574
  Кривая без истории:10575
  Кривая без истории:10576
  Кривая без истории:10577
  Кривая без истории:10578
  Кривая без истории:10579
  Кривая без истории:10580
  Кривая без истории:10581
  Кривая без истории:10582
  Кривая без истории:10583
  Кривая без истории:10584
  Кривая без истории:10585
  Кривая без истории:10586
  Кривая без истории:10587
  Кривая без истории:10588
  Кривая без истории:10589
  Кривая без истории:10590
  Кривая без истории:10591
  Кривая без истории:10592
  Кривая без истории:10593
  Кривая без истории:10594
  Кривая без истории:10595
  Кривая без истории:10596
  Кривая без истории:10597
  Кривая без истории:10598
  Кривая без истории:10599
  Кривая без истории:10600
  Кривая без истории:10601
  Кривая без истории:10602
  Кривая без истории:10603
  Кривая без истории:10604
  Кривая без истории:10605
  Кривая без истории:10606
  Кривая без истории:10607
  Кривая без истории:10608
  Кривая без истории:10609
  Кривая без истории:10610
  Кривая без истории:10611
  Кривая без истории:10612
  Кривая без истории:10613
  Кривая без истории:10614
  Кривая без истории:10615
  Кривая без истории:10616
  Кривая без истории:10617
  Кривая без истории:10618
  Кривая без истории:10619
  Кривая без истории:10620
  Кривая без истории:10621
  Кривая без истории:10622
  Кривая без истории:10623
  Кривая без истории:10624
  Кривая без истории:10625
  Кривая без истории:10626
  Кривая без истории:10627
  Кривая без истории:10628
  Кривая без истории:10629
  Кривая без истории:10630
  Кривая без истории:10631
  Кривая без истории:10632
  Кривая без истории:10633
  Кривая без истории:10634
  Кривая без истории:10635
  Кривая без истории:10636
  Кривая без истории:10637
  Кривая без истории:10638
  Кривая без истории:10639
  Кривая без истории:10640
  Кривая без истории:10641
  Кривая без истории:10642
  Кривая без истории:10643
  Кривая без истории:10644
  Кривая без истории:10645
  Кривая без истории:10646
  Кривая без истории:10647
  Кривая без истории:10648
  Кривая без истории:10649
  Кривая без истории:10650
  Кривая без истории:10651
  Кривая без истории:10652
  Кривая без истории:10653
  Кривая без истории:10654
  Кривая без истории:10655
  Кривая без истории:10656
  Кривая без истории:10657
  Кривая без истории:10658
  Кривая без истории:10659
  Кривая без истории:10660
  Кривая без истории:10661
  Кривая без истории:10662
  Кривая без истории:10663
  Кривая без истории:10664
  Кривая без истории:10665
  Кривая без истории:10666
  Кривая без истории:10667
  Кривая без истории:10668
  Кривая без истории:10669
  Кривая без истории:10670
  Кривая без истории:10671
  Кривая без истории:10672
  Кривая без истории:10673
  Кривая без истории:10674
  Кривая без истории:10675
  Кривая без истории:10676
  Кривая без истории:10677
  Кривая без истории:10678
  Кривая без истории:10679
  Кривая без истории:10680
  Кривая без истории:10681
  Кривая без истории:10682
  Кривая без истории:10683
  Кривая без истории:10684
  Кривая без истории:10685
  Кривая без истории:10686
  Кривая без истории:10687
  Кривая без истории:10688
  Кривая без истории:10689
  Кривая без истории:10690
  Кривая без истории:10691
  Кривая без истории:10692
  Кривая без истории:10693
  Кривая без истории:10694
  Кривая без истории:10695
  Кривая без истории:10696
  Кривая без истории:10697
  Кривая без истории:10698
  Кривая без истории:10699
  Кривая без истории:10700
  Кривая без истории:10701
  Кривая без истории:10702
  Кривая без истории:10703
  Кривая без истории:10704
  Кривая без истории:10705
  Кривая без истории:10706
  Кривая без истории:10707
  Кривая без истории:10708
  Кривая без истории:10709
  Кривая без истории:10710
  Кривая без истории:10711
  Кривая без истории:10712
  Кривая без истории:10713
  Кривая без истории:10714
  Кривая без истории:10715
  Кривая без истории:10716
  Кривая без истории:10717
  Кривая без истории:10718
  Кривая без истории:10719
  Кривая без истории:10720
  Кривая без истории:10721
  Кривая без истории:10722
  Кривая без истории:10723
  Кривая без истории:10724
  Кривая без истории:10725
  Кривая без истории:10726
  Кривая без истории:10727
  Кривая без истории:10728
  Кривая без истории:10729
  Кривая без истории:10730
  Кривая без истории:10731
  Кривая без истории:10732
  Кривая без истории:10733
  Кривая без истории:10734
  Кривая без истории:10735
  Кривая без истории:10736
  Кривая без истории:10737
  Кривая без истории:10738
  Кривая без истории:10739
  Кривая без истории:10740
  Кривая без истории:10741
  Кривая без истории:10742
  Кривая без истории:10743
  Кривая без истории:10744
  Кривая без истории:10745
  Кривая без истории:10746
  Кривая без истории:10747
  Кривая без истории:10748
  Кривая без истории:10749
  Кривая без истории:10750
  Кривая без истории:10751
  Кривая без истории:10752
  Кривая без истории:10753
  Кривая без истории:10754
  Кривая без истории:10755
  Кривая без истории:10756
  Кривая без истории:10757
  Кривая без истории:10758
  Кривая без истории:10759
  Кривая без истории:10760
  Кривая без истории:10761
  Кривая без истории:10762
